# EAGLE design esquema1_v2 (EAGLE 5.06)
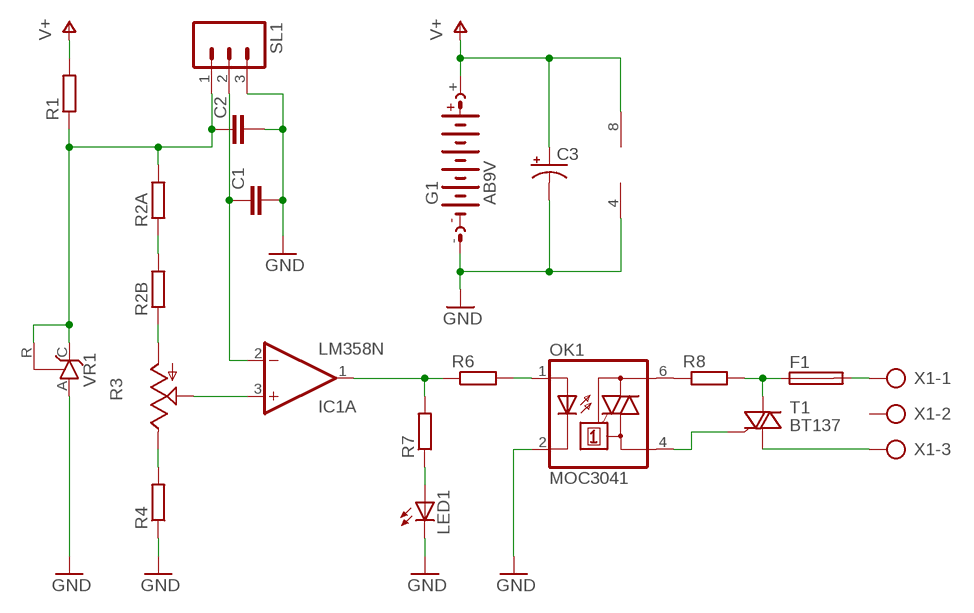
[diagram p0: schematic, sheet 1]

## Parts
C1  C-EU050-024X044  [C050-024X044]
C2  C-EU050-024X044  [C050-024X044]
C3  CPOL-USE2.5-6  [E2,5-6]
F1  SH22  [SH22]
G1  AB9V  [AB9V]
IC1  LM358N  [DIL08]
LED1  LED3MM  [LED3MM]
OK1  MOC3041  IL410  [DIL06]
R1  R-EU_0207/10  [0207/10]
R2A  R-EU_0207/10  [0207/10]
R2B  R-EU_0207/10  [0207/10]
R3  TRIM_US-B25U  [B25U]
R4  R-EU_0207/10  [0207/10]
R6  R-EU_0207/10  [0207/10]
R7  R-EU_0207/10  [0207/10]
R8  R-EU_0207/10  [0207/10]
SL1  M03  [03P]
T1  BT137  TIC225S  [TO220DS]
VR1  TL431CLP  [TO92-CLP]
X1  AK500/3  [AK500/3]

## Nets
GND: C1.2 C2.2 C3.- G1.- IC1.4(P:V-) LED1.K(C) OK1.2(C) R4.1 SL1.3 VR1.A
N$1: C2.1 R1.1 R2A.2 SL1.1 VR1.C VR1.R
N$2: R3.E R4.2
N$4: R2B.1 R3.A
N$5: R2A.1 R2B.2
N$6: C1.1 IC1.2(A:-IN) SL1.2
N$7: IC1.1(A:OUT) R6.1 R7.2
N$8: LED1.A R7.1
N$9: OK1.1(A) R6.2
N$10: OK1.6(A2) R8.1
N$11: F1.1 R8.2 T1.A2
N$12: F1.2 X1.1
N$13: OK1.4(A1) T1.G
N$14: T1.A1 X1.3
N$15: IC1.3(A:+IN) R3.S
V+: C3.+ G1.+ IC1.8(P:V+) R1.2
Unconnected: IC1.5(B:+IN) IC1.6(B:-IN) IC1.7(B:OUT) X1.2

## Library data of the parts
C1 C2 = rcl:C-EU: CAPACITOR, European symbol
C3 = rcl:CPOL-US: POLARIZED CAPACITOR, American symbol
F1 = fuse:SH22: FUSE HOLDER
G1 = battery:AB9V: 9-V BATTERY CLIP
IC1 = linear:LM358: OP AMP
LED1 = led:LED: LED
OK1 = optocoupler:IL410: SIEMENS OPTO COUPLER
R1 R2A R2B R4 R6-R8 = rcl:R-EU_: RESISTOR, European symbol
R3 = pot:TRIM_US-: POTENTIOMETER
SL1 = con-amp-quick:M03: AMP QUICK CONNECTOR
T1 = triac:TIC225S: TRIAC
VR1 = v-reg:TL431CLP: VOLTAGE REGULATOR
X1 = con-ptr500:AK500/3: CONNECTOR

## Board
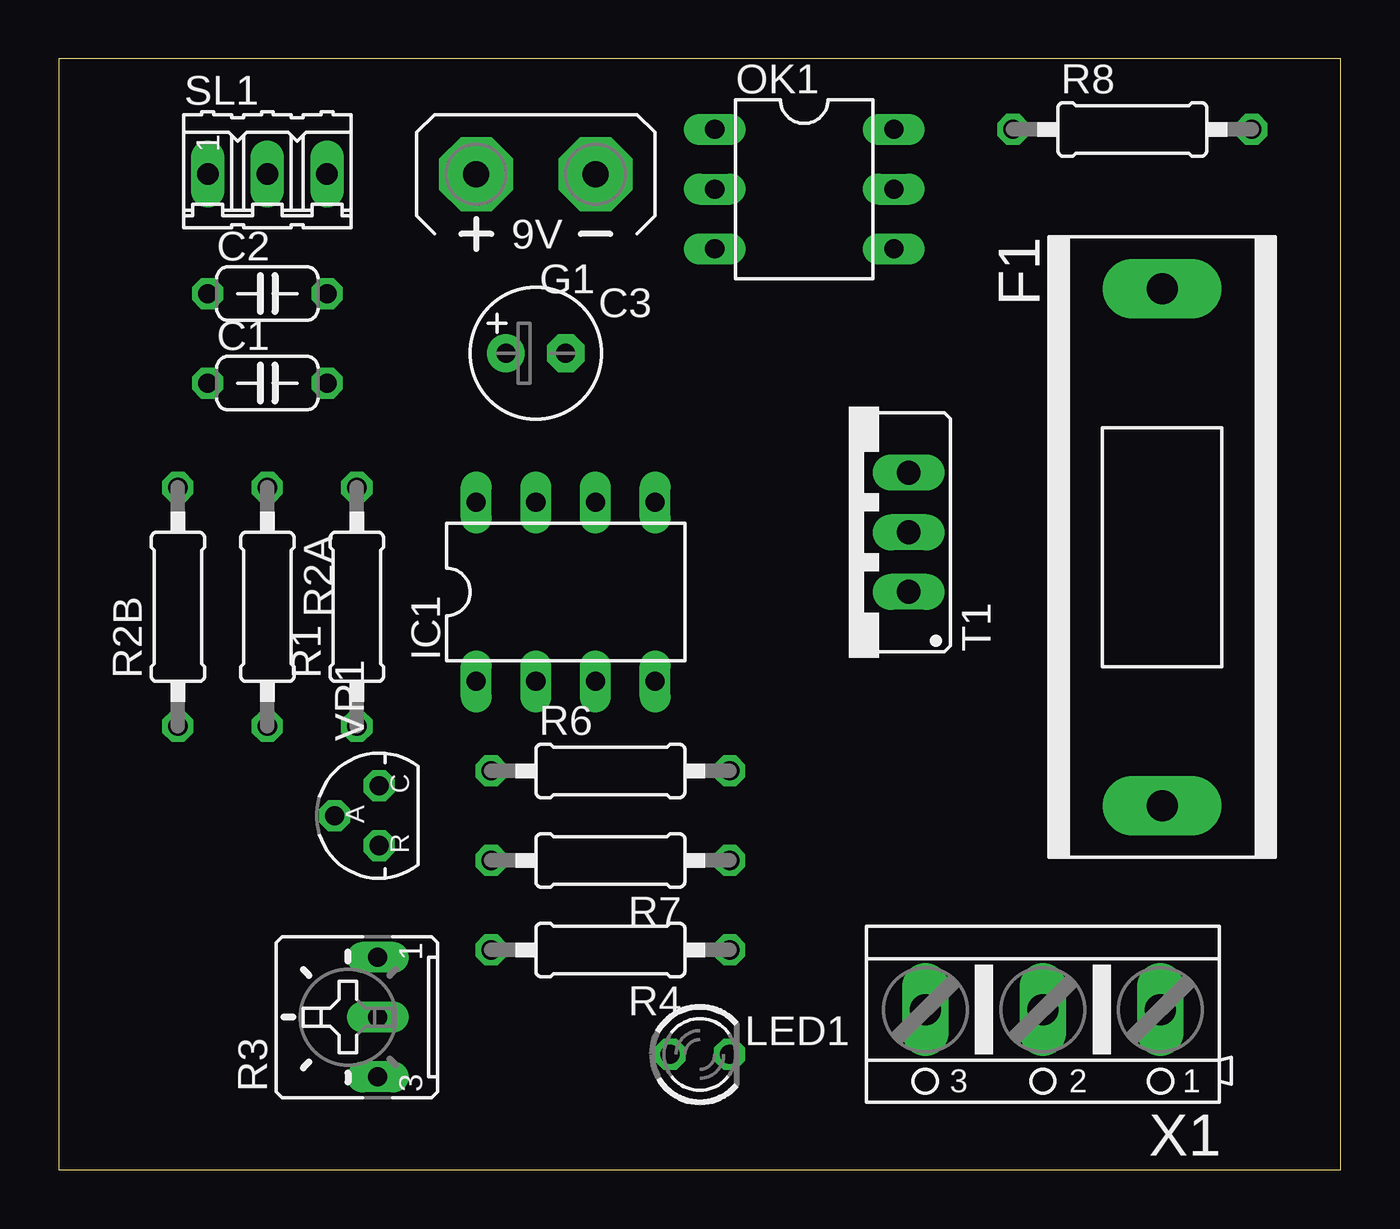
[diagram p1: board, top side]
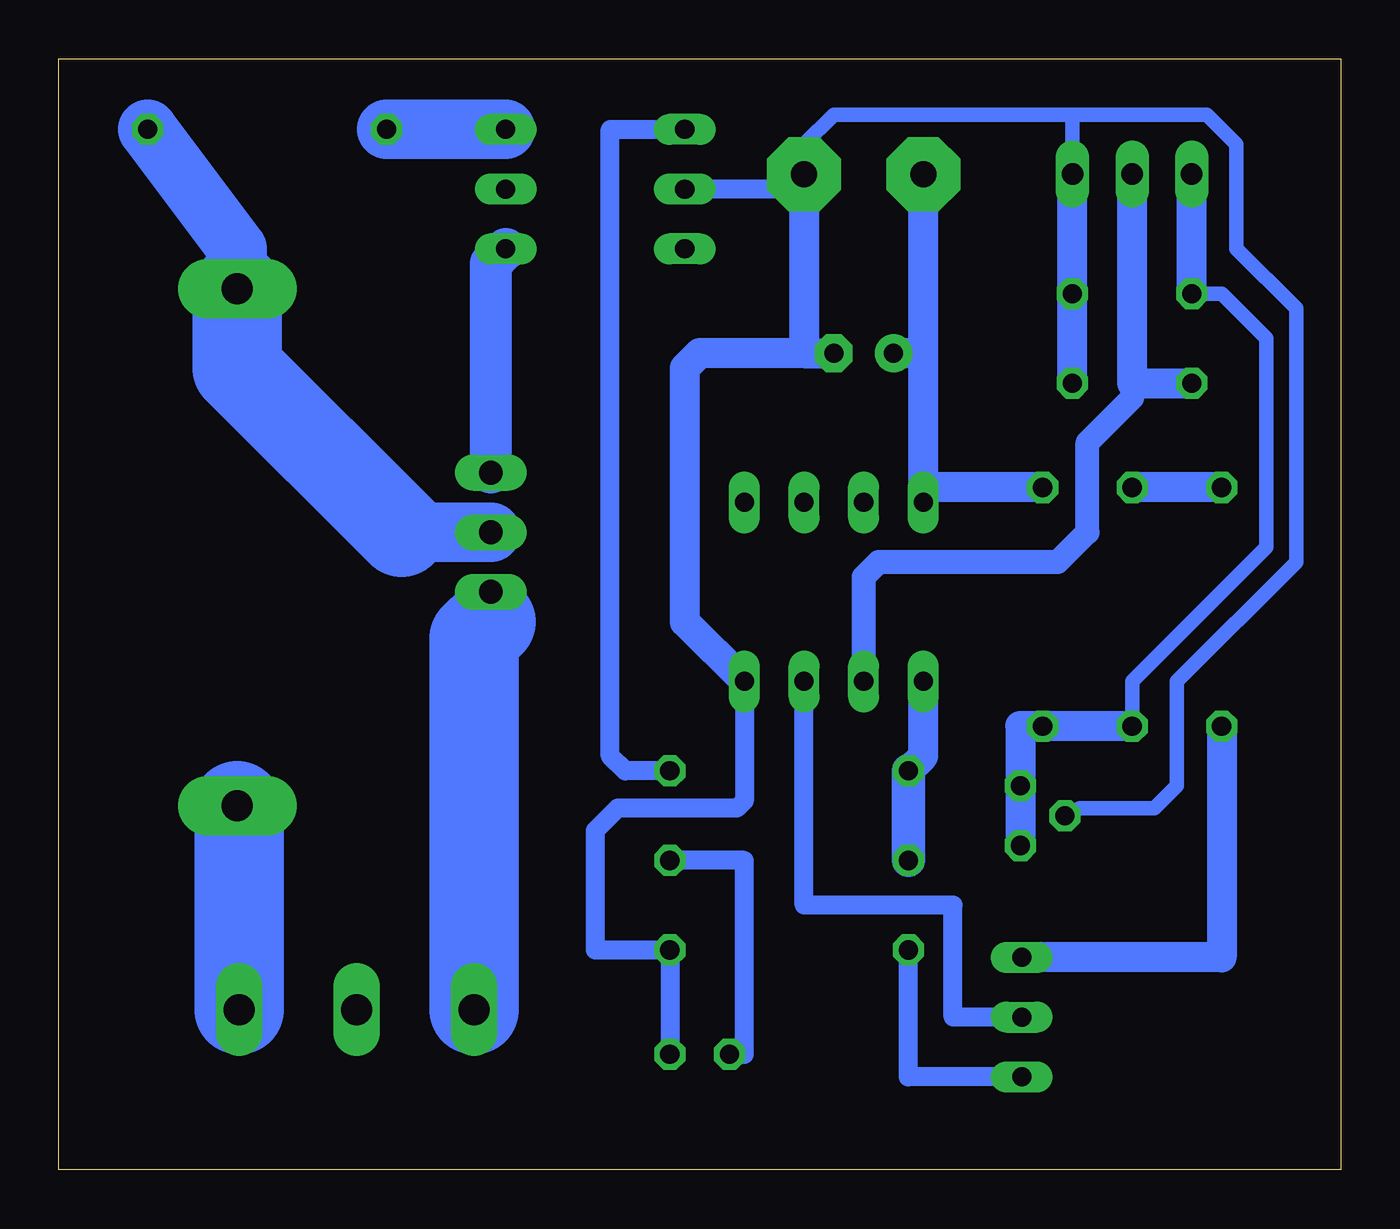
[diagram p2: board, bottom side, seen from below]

Size 54.59 x 47.3 mm. Coordinates in mm from the lower left corner, seen from the top.
Outline: 0,0 54.59,0 54.59,47.3 0,47.3 0,0
Copper layers (1*16): Top 0.035mm / dielectric 1.5mm / Bottom 0.035mm
Design rules "default": minimum track width 10mil, minimum drill 24mil, track to track 8mil, track to pad 8mil, pad to pad 8mil, via to via 8mil, smd to smd 8mil, copper to edge 40mil, drill to drill 8mil, minimum pad ring 10mil, minimum via ring 8mil, stop-mask expansion 4mil, vias tented up to drill 0mil, thermal gap 10mil

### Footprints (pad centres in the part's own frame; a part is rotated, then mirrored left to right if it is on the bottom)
C050-024X044 = drill 0.813 octagon: 1 -2.54,0; 2 2.54,0
E2,5-6 = drill 0.813 pad 1.6 round: + -1.27,0 | drill 0.813 pad 1.6 octagon: - 1.27,0
SH22 = drill 1.321 pad 2.54 long: 1 -10.998,0; 2 10.998,0
AB9V = drill 1.118 pad 3.15 octagon: + 0,2.54; - 0,-2.54
DIL08 = drill 0.813 long: 1 -3.81,-3.81; 2 -1.27,-3.81; 3 1.27,-3.81; 4 3.81,-3.81; 5 3.81,3.81; 6 1.27,3.81; 7 -1.27,3.81; 8 -3.81,3.81
LED3MM = drill 0.813 octagon: A -1.27,0; K 1.27,0
DIL06 = drill 0.813 long: 1 -2.54,-3.81; 2 0,-3.81; 3 2.54,-3.81; 4 2.54,3.81; 5 0,3.81; 6 -2.54,3.81
0207/10 = drill 0.813 octagon: 1 -5.08,0; 2 5.08,0
B25U = drill 0.813 long: A 2.54,-0.889; E -2.54,-0.889; S 0,-0.889
03P = drill 0.914 long: 1 -2.54,0; 2 0,0; 3 2.54,0
TO220DS = drill 1.016 long: A1 -2.54,-2.54; A2 0,-2.54; G 2.54,-2.54
TO92-CLP = drill 0.813 octagon: A 0,1.905; C 1.27,0; R -1.27,0
AK500/3 = drill 1.321 long: 1 -5.004,0; 2 0,0; 3 5.004,0

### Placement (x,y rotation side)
C1  8.88,33.49 0 top
C2  8.88,37.3 0 top
C3  20.32,34.76 0 top
F1  46.98,26.51 270 top
G1  20.32,42.38 90 top
IC1  21.59,24.6 0 top
LED1  27.3,4.92 0 top
OK1  31.75,41.74 270 top
R1  12.69,23.96 90 top
R2A  8.88,23.96 270 top
R2B  5.08,23.96 90 top
R3  12.69,6.5 90 top
R4  23.49,9.36 180 top
R6  23.49,16.98 0 top
R7  23.49,13.17 180 top
R8  45.71,44.29 0 top
SL1  8.88,42.38 0 top
T1  33.65,27.14 90 top
VR1  13.65,15.08 90 top
X1  41.9,6.82 180 top

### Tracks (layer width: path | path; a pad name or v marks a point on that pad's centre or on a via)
GND
  Bottom 0.61: G1.- 22.86,43.65 21.59,44.92 11.42,44.92 | 11.42,44.92 5.71,44.92 4.44,43.65 4.44,39.2 1.9,36.66 1.9,25.87 6.98,20.79 6.98,16.35 7.93,15.39 11.11,15.39 VR1.A | 11.42,44.92 C1.2
  Bottom 0.813: IC1.4 25.39,15.71 25.71,15.39 30.79,15.39 31.75,14.44 31.75,9.36 R4.1 LED1.K | 22.86,41.74 OK1.2
  Bottom 1.27: SL1.3 C2.2 C1.2 | G1.- 22.86,41.74 22.86,34.76 | 22.86,34.76 27.3,34.76 27.94,34.12 27.94,23.33 IC1.4 | 22.86,34.76 C3.-
N$1
  Bottom 0.61: C2.1 5.08,37.3 3.17,35.4 3.17,26.51 8.88,20.79 R2A.2
  Bottom 1.27: C2.1 SL1.1 | R2A.2 R1.1 13.65,18.89 VR1.C VR1.R
N$2
  Bottom 0.813: R3.E 18.41,3.96 R4.2
N$4
  Bottom 1.27: R3.A 5.08,9.04 R2B.1
N$5
  Bottom 1.27: R2B.2 R2A.1
N$6
  Bottom 1.016: 8.88,33.49 8.88,32.86 10.79,30.95 10.79,27.14 12.06,25.87 19.68,25.87 20.32,25.23 IC1.2
  Bottom 1.27: SL1.2 8.88,33.49 C1.1
N$7
  Bottom 1.27: IC1.1 17.78,17.62 R6.1
  Bottom 1.422: R6.1 R7.2
N$8
  Bottom 0.813: R7.1 25.39,13.17 25.39,4.92 LED1.A
N$9
  Bottom 0.813: R6.2 30.48,16.98 31.11,17.62 31.11,44.29 OK1.1
N$10
  Bottom 2.54: OK1.6 R8.1
N$11
  Bottom 2.54: 46.98,37.94 F1.1 46.98,39.2 R8.2 | T1.A2 40,27.14
  Bottom 3.81: F1.1 46.98,34.12 40,27.14
N$12
  Bottom 3.81: F1.2 46.98,15.08 46.91,15.08 X1.1
N$13
  Bottom 1.778: T1.G 36.19,38.57 OK1.4
N$14
  Bottom 1.016: 36.19,23.33 T1.A1
  Bottom 3.81: X1.3 36.9,22.62 36.19,23.33
N$15
  Bottom 0.813: IC1.3 22.86,11.27 16.51,11.27 16.51,6.5 R3.S
V+
  Bottom 1.27: 17.78,29.05 17.78,34.76 | 17.78,34.76 G1.+ | IC1.8 17.78,29.05 | 17.78,34.76 C3.+ | R1.2 17.78,29.05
